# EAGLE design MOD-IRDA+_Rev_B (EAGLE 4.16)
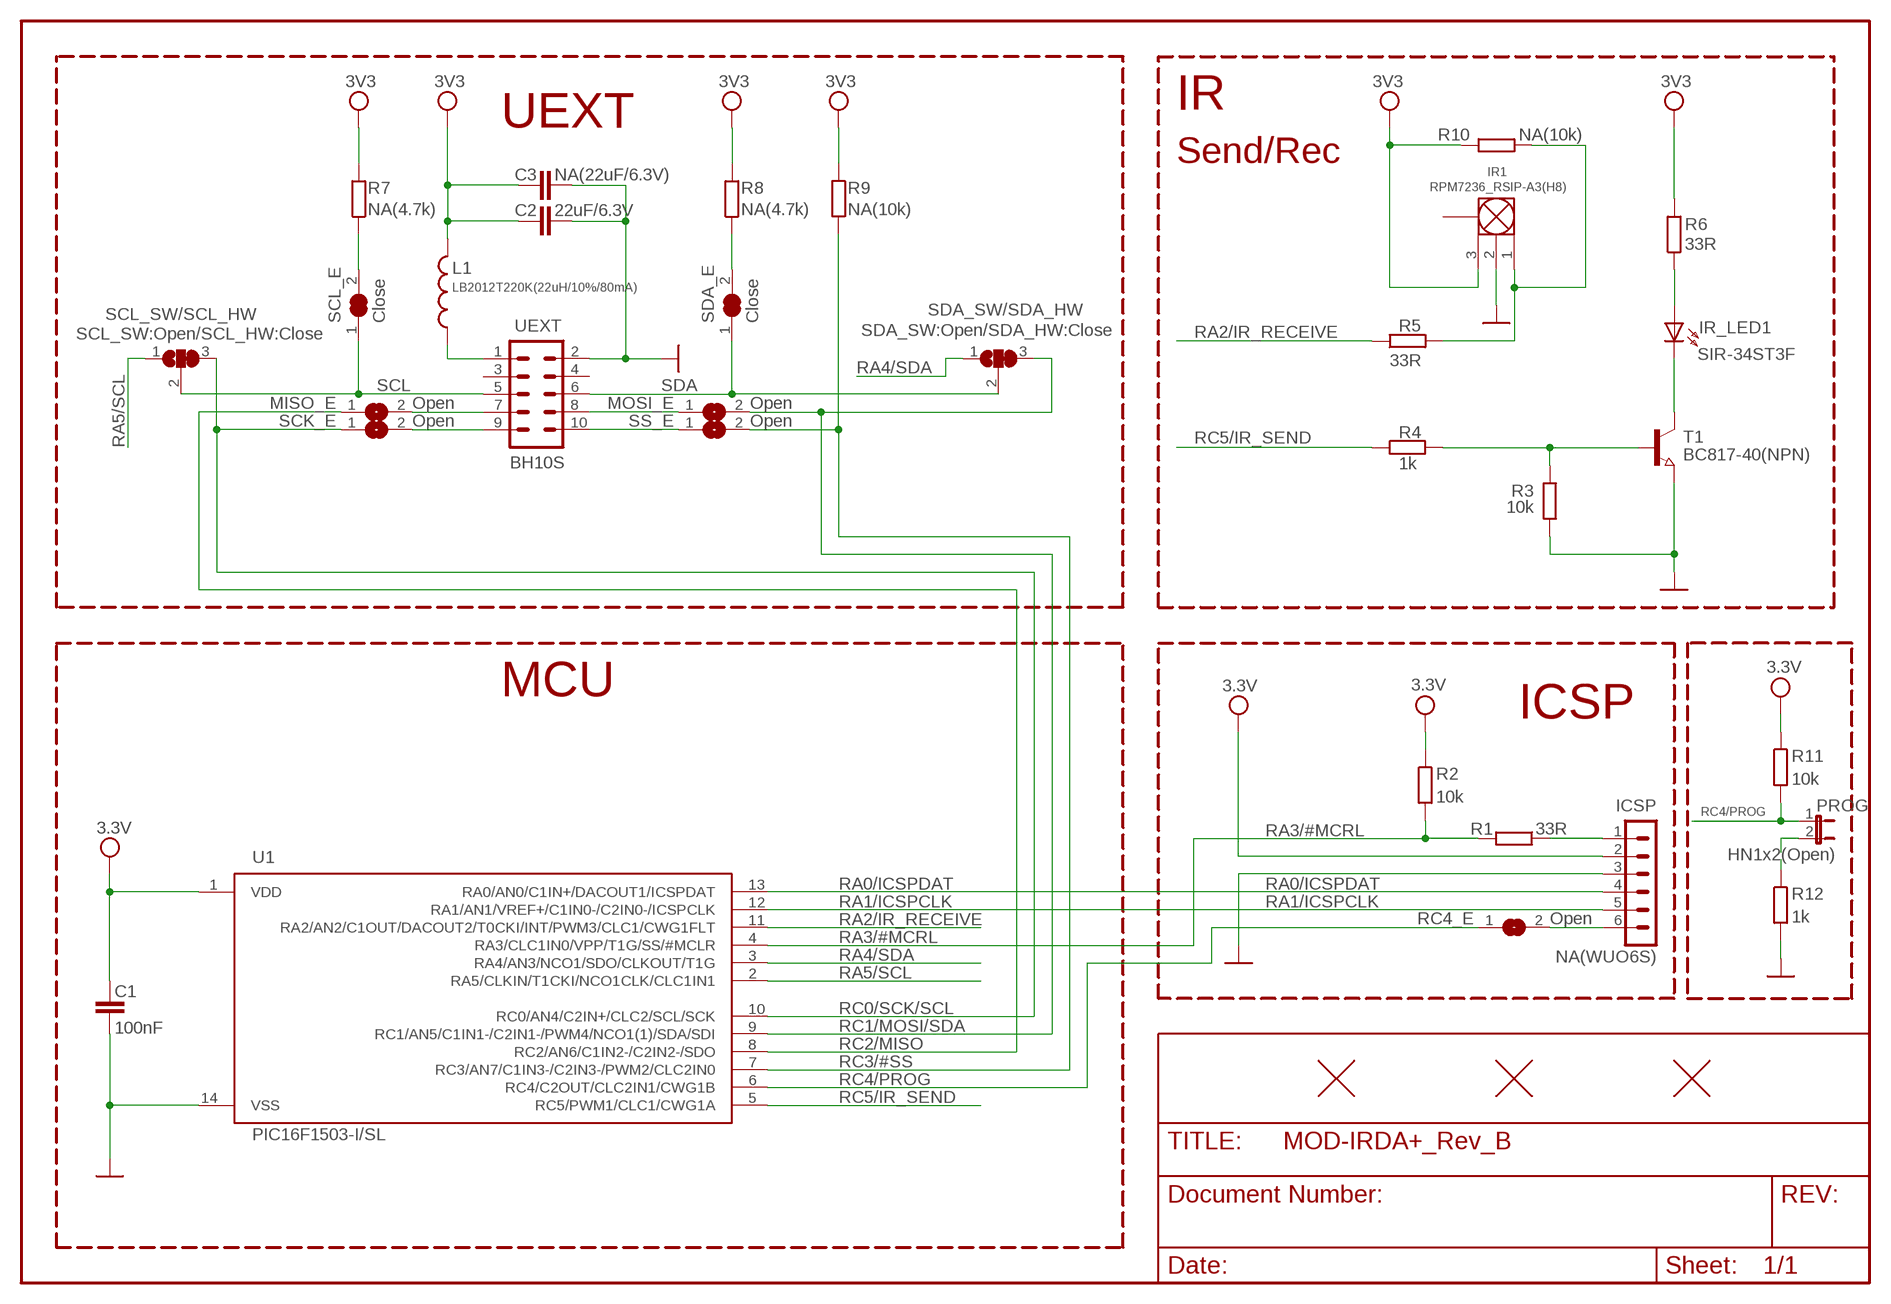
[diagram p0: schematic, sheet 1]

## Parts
C1  100nF  C-EUC0603_DWS  [C0603_DWS]
C2  22uF/6.3V  C-EUC0603_DWS  [C0603_DWS]
C3  NA(22uF/6.3V)  C-EUC0603_DWS  [C0603_DWS]
FID1  FIDUCIAL1X2  [FIDUCIAL-1X2]
FID2  FIDUCIAL1X2  [FIDUCIAL-1X2]
FID3  FIDUCIAL1X2  [FIDUCIAL-1X2]
ICSP  NA(WUO6S)  CON6WUO6S  [WU06S]
IR1  RPM7236_RSIP-A3(H8)  RPM7236  [RPM7236]
IR_LED1  SIR-34ST3F  LED3.0MM  [LED-3.0MM]
L1  LB2012T220K(22uH/10%/80mA)  L-USL0805_5MIL_DWS  [L0805_5MIL_DWS]
MISO_E  Open  SJSJ_SMALLER  [SJ_1_SMALLER]
MOSI_E  Open  SJSJ_SMALLER  [SJ_1_SMALLER]
PROG  HN1x2(Open)  JP1E  [JP1]
R1  33R  R-EU_R0603_5MIL_DWS  [R0603_5MIL_DWS]
R2  10k  R-EU_R0603_5MIL_DWS  [R0603_5MIL_DWS]
R3  10k  R-EU_R0603_5MIL_DWS  [R0603_5MIL_DWS]
R4  1k  R-EU_R0603_5MIL_DWS  [R0603_5MIL_DWS]
R5  33R  R-EU_R0603_5MIL_DWS  [R0603_5MIL_DWS]
R6  33R  R-EU_R0805_5MIL_DWS  [R0805_5MIL_DWS]
R7  NA(4.7k)  R-EU_R0603_5MIL_DWS  [R0603_5MIL_DWS]
R8  NA(4.7k)  R-EU_R0603_5MIL_DWS  [R0603_5MIL_DWS]
R9  NA(10k)  R-EU_R0603_5MIL_DWS  [R0603_5MIL_DWS]
R10  NA(10k)  R-EU_R0603_5MIL_DWS  [R0603_5MIL_DWS]
R11  10k  R-EU_R0603_5MIL_DWS  [R0603_5MIL_DWS]
R12  1k  R-EU_R0603_5MIL_DWS  [R0603_5MIL_DWS]
RC4_E  Open  SJSJ_SMALLER  [SJ_1_SMALLER]
SCK_E  Open  SJSJ_SMALLER  [SJ_1_SMALLER]
SCL_E  Close  SJSJ_1_SMALLER_CLOSE  [SJ_1_SMALLER_CLOSE]
SCL_SW/SCL_HW  SCL_SW:Open/SCL_HW:Close  SJ2W5  [SJ_2_SMALL_23_TIED]
SDA_E  Close  SJSJ_1_SMALLER_CLOSE  [SJ_1_SMALLER_CLOSE]
SDA_SW/SDA_HW  SDA_SW:Open/SDA_HW:Close  SJ2W5  [SJ_2_SMALL_23_TIED]
SS_E  Open  SJSJ_SMALLER  [SJ_1_SMALLER]
T1  BC817-40(NPN)  NPN-TRANSISTOR_SOT23  [SOT23]
U1  PIC16F1503-I/SL  PIC16F1503  [SOIC14]
UEXT  BH10S  ML10SMD  [ML10_PADS]

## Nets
GND: C1.2 C2.2 C3.2 ICSP.3 IR1.2(GND) R3.2 R12.2 T1.2(E) U1.14(VSS) UEXT.2
N$1: IR_LED1.K(C) T1.3(C)
N$2: IR1.1(VOUT) R5.2 R10.2
N$3: IR_LED1.A R6.1
N$4: R3.1 R4.2 T1.1(B)
N$5: MISO_E.2 UEXT.7
N$6: R7.1 SCL_E.2
N$7: R8.1 SDA_E.2
N$8: SCK_E.2 UEXT.9
N$9: ICSP.6 RC4_E.2
N$10: SS_E.1 UEXT.10
N$11: MOSI_E.1 UEXT.8
N$12: L1.1 UEXT.1
N$13: ICSP.1 R1.1
N$15: PROG.2 R12.1
RA0/ICSPDAT: ICSP.4 U1.13(RA0/AN0/C1IN+/DACOUT1/ICSPDAT)
RA1/ICSPCLK: ICSP.5 U1.12(RA1/AN1/VREF+/C1IN0-/C2IN0-/ICSPCLK)
RA2/IR_RECEIVE: R5.1 U1.11(RA2/AN2/C1OUT/DACOUT2/T0CKI/INT/PWM3/CLC1/CWG1FLT)
RA3/#MCRL: R1.2 R2.2 U1.4(RA3/CLC1IN0/VPP/T1G/SS/#MCLR)
RA4/SDA: SDA_SW/SDA_HW.1 U1.3(RA4/AN3/NCO1/SDO/CLKOUT/T1G)
RA5/SCL: SCL_SW/SCL_HW.1 U1.2(RA5/CLKIN/T1CKI/NCO1CLK/CLC1IN1)
RC0/SCK/SCL: SCK_E.1 SCL_SW/SCL_HW.3 U1.10(RC0/AN4/C2IN+/CLC2/SCL/SCK)
RC1/MOSI/SDA: MOSI_E.2 SDA_SW/SDA_HW.3 U1.9(RC1/AN5/C1IN1-/C2IN1-/PWM4/NCO1(1)/SDA/SDI)
RC2/MISO: MISO_E.1 U1.8(RC2/AN6/C1IN2-/C2IN2-/SDO)
RC3/#SS: R9.2 SS_E.2 U1.7(RC3/AN7/C1IN3-/C2IN3-/PWM2/CLC2IN0)
RC4/PROG: PROG.1 R11.2 RC4_E.1 U1.6(RC4/C2OUT/CLC2IN1/CWG1B)
RC5/IR_SEND: R4.1 U1.5(RC5/PWM1/CLC1/CWG1A)
SCL: SCL_E.1 SCL_SW/SCL_HW.2 UEXT.5
SDA: SDA_E.1 SDA_SW/SDA_HW.2 UEXT.6
VCC: C1.1 C2.1 C3.1 ICSP.2 IR1.3(VCC) L1.2 R2.1 R6.2 R7.2 R8.2 R9.1 R10.1 R11.1 U1.1(VDD) ; supply symbol labelled 3V3, 3.3V
Unconnected: IR1.P$4 IR1.P$5 UEXT.3 UEXT.4

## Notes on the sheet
- IR
- UEXT
- Send/Rec
- MCU
- ICSP

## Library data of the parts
C1-C3 = rcl:C-EU: CAPACITOR, European symbol
FID1-FID3 = SparkFunEagle-6-6-07:FIDUCIAL: Fiducial Alignment Points
ICSP = Penko:CON6: CONNECTORS - 6 PINS
IR1 = OLIMEX_DISCRET:RPM7236
IR_LED1 = DOUBLE-SIDE:LED
L1 = rcl:L-US: INDUCTOR, American symbol
MISO_E MOSI_E RC4_E SCK_E SCL_E SDA_E SS_E = jumper:SJ: SMD solder JUMPER
PROG = jumper:JP1E: JUMPER
R1-R12 = rcl:R-EU_: RESISTOR, European symbol
SCL_SW/SCL_HW SDA_SW/SDA_HW = jumper:SJ2W: SMD solder JUMPER
T1 = semicon-smd-ipc:NPN-TRANSISTOR_: NPN TRANSISTOR
U1 = OLIMEX_IC:PIC16F1503
UEXT = con-harting-ml:ML10: HARTING

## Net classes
1 PWR: width 0.203 mm, drill 0.076 mm, clearance 0.4 mm

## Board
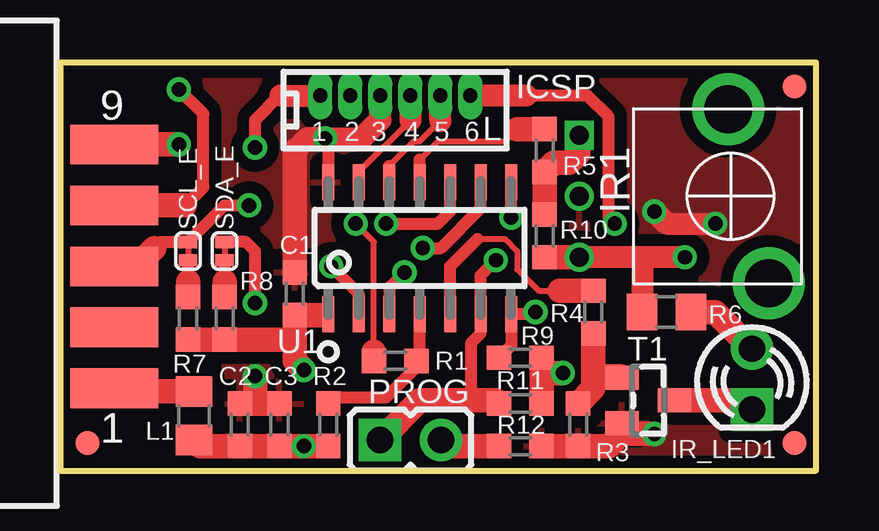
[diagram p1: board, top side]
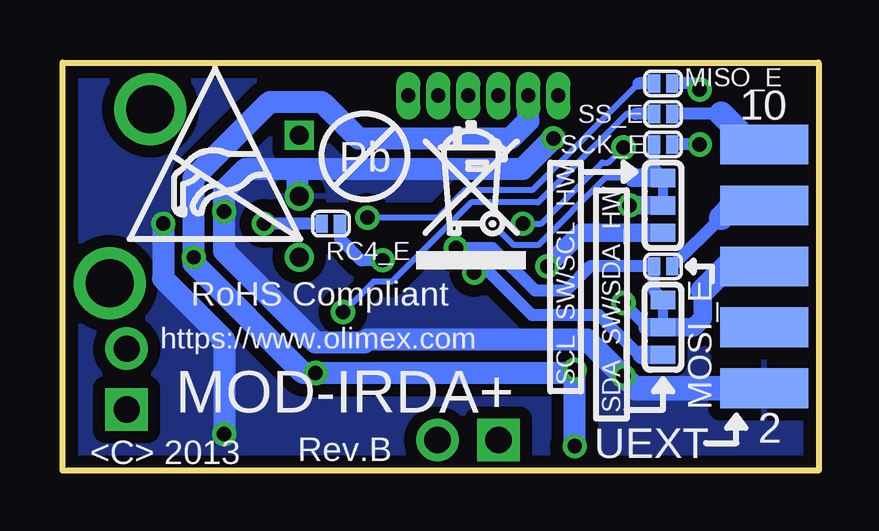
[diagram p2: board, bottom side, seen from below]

Size 31.5 x 17 mm. Coordinates in mm from the lower left corner, seen from the top.
Outline: 0,0 31.5,0 31.5,17 0,17 0,0
Copper layers (1+16): Top 0.035mm / dielectric 1.5mm / Bottom 0.035mm
Design rules "default": minimum track width 10mil, minimum drill 23mil, track to track 10mil, track to pad 10mil, pad to pad 10mil, via to via 10mil, smd to smd 1mil, copper to edge 10mil, drill to drill 8mil, minimum pad ring 7mil, minimum via ring 8mil, stop-mask expansion 4mil, vias tented up to drill 30mil, thermal gap 20mil

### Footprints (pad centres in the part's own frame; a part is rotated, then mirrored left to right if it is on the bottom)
C0603_DWS = smd 1.016 x 1.016: 1 -0.889,0; 2 0.889,0
FIDUCIAL-1X2 = smd 1 x 1: 1 0,0
WU06S = drill 0.6 pad 0.991 long: 1 -3.125,0; 2 -1.875,0; 3 -0.625,0; 4 0.625,0; 5 1.875,0; 6 3.125,0
RPM7236 = drill 0.8 square: 1 -2.54,-6.3 | drill 0.8 round: 2 0,-6.3; 3 2.54,-6.3 | drill 2 round: P$4 -3.63,-0.1; P$5 3.63,1.6
LED-3.0MM = drill 1.092 pad 1.778 round: A -1.27,0 | drill 1.092 pad 1.778 square: K 1.27,0
L0805_5MIL_DWS = smd 1.27 x 1.524: 1 -1.016,0; 2 1.016,0
SJ_1_SMALLER = smd 0.508 x 0.762: 1 -0.381,0; 2 0.381,0
JP1 = drill 1.1 pad 1.778 square: 1 0,-1.27 | drill 1.1 pad 1.778 round: 2 0,1.27
R0603_5MIL_DWS = smd 1.016 x 1.016: 1 -0.889,0; 2 0.889,0
R0805_5MIL_DWS = smd 1.27 x 1.524: 1 -1.016,0; 2 1.016,0
SJ_1_SMALLER_CLOSE = smd 0.508 x 0.762: 1 -0.381,0; 2 0.381,0
SJ_2_SMALL_23_TIED = smd 0.762 x 1.016: 1 -1.143,0; 2 0,0; 3 1.143,0
SOT23 = smd 1 x 1.4: 1 -0.95,-1.1; 2 0.95,-1.1; 3 0,1.1
SOIC14 = smd 0.5 x 1.5: 1 -3.81,-2.75; 2 -2.54,-2.75; 3 -1.27,-2.75; 4 0,-2.75; 5 1.27,-2.75; 6 2.54,-2.75; 7 3.81,-2.75; 8 3.81,2.75; 9 2.54,2.75; 10 1.27,2.75; 11 0,2.75; 12 -1.27,2.75; 13 -2.54,2.75; 14 -3.81,2.75
ML10_PADS = smd 1.651 x 3.683: 1 -5.08,-0.229; 3 -2.54,-0.229; 5 0,-0.229; 7 2.54,-0.229; 9 5.08,-0.229 | smd 1.651 x 3.683 bottom: 2 -5.08,-0.229; 4 -2.54,-0.229; 6 0,-0.229; 8 2.54,-0.229; 10 5.08,-0.229

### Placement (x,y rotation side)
C1  9.78,7.37 90 top
C2  7.49,1.91 90 top
C3  9.14,1.91 90 top
FID1  1.14,1.14 0 top
FID2  30.61,1.14 0 top
FID3  30.61,16 0 top
ICSP  13.97,15.62 0 top
IR1  27.94,11.43 270 top
IR_LED1  28.83,3.81 270 top
L1  5.59,2.29 270 top
MISO_E  6.48,16.13 0 bottom
MOSI_E  6.48,8.51 180 bottom
PROG  14.61,1.27 270 top
R1  13.97,4.57 0 top
R2  11.18,1.91 90 top
R3  21.59,1.91 270 top
R4  22.23,6.6 270 top
R5  20.19,13.34 270 top
R6  25.27,6.6 180 top
R7  5.33,6.35 270 top
R8  6.86,6.35 270 top
R9  19.18,4.7 180 top
R10  20.19,9.78 90 top
R11  19.18,2.79 180 top
R12  19.18,1.02 0 top
RC4_E  20.32,10.29 180 bottom
SCK_E  6.48,13.59 0 bottom
SCL_E  5.33,9.14 270 top
SCL_SW/SCL_HW  6.48,11.05 90 bottom
SDA_E  6.86,9.14 270 top
SDA_SW/SDA_HW  6.48,5.97 90 bottom
SS_E  6.48,14.86 180 bottom
T1  24.51,2.92 270 top
U1  14.99,9.27 0 top
U$1  [ESD_SYMBOL]  28.7,9.65 0 bottom
U$2  [RECYCLE_BIN1/8]  16.76,8.38 0 bottom
U$3  [PB_SMALL]  18.92,13.08 0 bottom
UEXT  2.03,8.51 90 top

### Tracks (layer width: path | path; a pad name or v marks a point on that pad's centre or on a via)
GND  (via drill 0.6)
  Top 0.508: U1.14 11.18,13.72 v11.05,13.84
  Top 0.914: ICSP.3 13.35,14.62 12.57,13.84 v11.05,13.84 10.29,13.84 9.78,13.34 | v24.77,10.79 25.27,10.29 v27.3,10.29
  Top 1.016: 8.13,2.79 C3.2 | 9.78,13.34 C1.2 | v8.13,3.94 8.13,2.79 | 8.13,2.79 C2.2 | R12.2 R3.2 22.86,1.02 23.37,1.52 | v24.77,1.52 23.37,1.52 | T1.2 23.37,1.93 23.37,1.52
  Bottom 0.914: v11.05,13.84 12.32,12.57 21.72,12.57 | 7.62,3.43 v8.13,3.94 9.65,5.46 18.8,5.46 18.92,5.33 20.95,5.33 24.77,9.14 v24.77,10.79 24.77,11.68 23.88,12.57 21.72,12.57 | v24.77,1.52 24.77,5.46 27.3,8 v27.3,10.29 | IR1.2 21.72,11.51 21.72,12.57
  Bottom 1.016: UEXT.2 7.62,3.43
  pour Bottom (isolate 0.508): -10.54,19.3 38.1,19.3 38.1,-2.54 -10.54,-2.54
  pour Top (isolate 0.508): -9.53,18.03 33.02,18.03 33.02,-1.27 -9.53,-1.27
N$1
  Top 1.016: T1.3 28.45,2.92 IR_LED1.K
N$2
  Top 1.016: IR1.1 21.59,13.92 21.59,13.21 21.21,12.83 20.57,12.83 R5.2 R10.2
N$3
  Top 1.016: R6.1 27.3,6.6 IR_LED1.A
N$4
  Top 1.016: R3.1 22.23,3.43 22.23,3.94 | 22.23,3.94 R4.2 | T1.1 23.34,3.94 22.23,3.94
N$5  (via drill 0.6)
  Top 0.508: 5.21,11.05 5.97,11.81 5.97,14.86 v4.95,15.88
  Top 1.016: UEXT.7 5.21,11.05
  Bottom 0.508: v4.95,15.88 5.21,16.13 MISO_E.2
N$6
  Top 0.508: 5.33,7.87 SCL_E.2
  Top 1.016: R7.1 5.33,7.87
N$7
  Top 0.508: 6.86,7.87 SDA_E.2
  Top 1.016: R8.1 6.86,7.87
N$8  (via drill 0.6)
  Top 1.016: UEXT.9 v4.95,13.59
  Bottom 0.508: v4.95,13.59 SCK_E.2
N$9  (via drill 0.6)
  Top 0.508: v23.11,10.29 22.86,10.54 22.86,14.73 21.97,15.62 19.43,15.62
  Top 0.914: 19.43,15.62 ICSP.6
  Bottom 0.508: RC4_E.2 v23.11,10.29
N$10
  Bottom 0.508: UEXT.10 2.52,13.34 | 4.06,14.86 SS_E.1
  Bottom 0.762: 2.52,13.34 2.54,13.34
  Bottom 1.016: 2.54,13.34 4.06,14.86
N$11
  Bottom 0.508: 4.06,10.54 MOSI_E.1
  Bottom 1.016: UEXT.8 3.56,11.05 4.06,10.54
N$12
  Top 1.016: UEXT.1 2.39,3.3 L1.1
N$13  (via drill 0.6)
  Top 0.254: 13.08,4.95 13.08,9.53 v12.32,10.29
  Top 0.508: 9.19,15.62 9.14,15.62 8.13,14.61 v8.13,13.46
  Top 0.914: 9.19,15.62 ICSP.1
  Top 1.016: R1.1 13.08,4.95
  Bottom 0.254: v12.32,10.29 11.56,10.29 9.02,12.83 8.76,12.83 v8.13,13.46
N$15
  Top 1.016: R12.1 16.13,1.02 PROG.2
RA0/ICSPDAT
  Top 0.254: U1.13 12.45,12.45 14.61,14.61
  Top 0.508: ICSP.4
  Top 0.914: 14.61,14.61 ICSP.4
RA1/ICSPCLK
  Top 0.254: 13.72,12.7 14.73,13.72 14.99,13.72 15.85,14.57
  Top 0.508: U1.12 13.72,12.7
  Top 0.914: 15.85,14.57 ICSP.5
RA2/IR_RECEIVE
  Top 0.254: 14.99,12.95 15.75,13.72 18.54,13.72 19.05,14.22
  Top 0.508: U1.11 14.99,12.95
  Top 1.016: 19.05,14.22 R5.1
RA3/#MCRL
  Top 0.508: R2.2 11.43,3.05 13.59,3.05 14.86,4.32 R1.2 14.99,4.57 U1.4
RA4/SDA  (via drill 0.6)
  Top 0.508: v14.35,8.26 13.72,7.62 U1.3
  Bottom 0.508: v14.35,8.26 13.72,8.26 11.94,6.48 9.14,6.48 7.49,4.83 7.37,4.83
  Bottom 0.762: SDA_SW/SDA_HW.1 7.37,4.83
RA5/SCL  (via drill 0.6)
  Top 0.508: v11.3,8.51 12.45,7.37 U1.2
  Bottom 0.762: v11.3,8.51 9.91,9.91 SCL_SW/SCL_HW.1
RC0/SCK/SCL  (via drill 0.6)
  Top 0.508: v13.59,10.29 15.75,10.29 16.26,10.79 U1.10
  Bottom 0.254: v13.59,10.29 12.7,9.4 11.68,9.4 8.89,12.19 7.75,12.19
  Bottom 0.508: SCL_SW/SCL_HW.3 6.86,12.57 SCK_E.1
  Bottom 0.762: SCL_SW/SCL_HW.3 7.75,12.19
RC1/MOSI/SDA  (via drill 0.6)
  Top 0.508: U1.9 17.53,10.92 15.88,9.27 v15.11,9.27
  Bottom 0.508: v15.11,9.27 13.59,9.27 11.81,7.49 10.54,7.49 9.53,8.51 MOSI_E.2 6.86,7.49 SDA_SW/SDA_HW.3
RC2/MISO  (via drill 0.6)
  Top 0.508: v18.8,10.54 U1.8
  Bottom 0.254: 7.49,16.13 11.94,11.68 14.73,11.68 15.88,10.54 v18.8,10.54
  Bottom 0.508: MISO_E.1 7.49,16.13
RC3/#SS  (via drill 0.6)
  Top 0.508: R9.2 18.8,5.21 U1.7 19.73,6.52 v19.81,6.6
  Bottom 0.254: 7.62,14.86 8,14.86 11.68,11.18 14.48,11.18 17.78,7.87 18.54,7.87 v19.81,6.6
  Bottom 0.508: SS_E.2 7.62,14.86
RC4/PROG  (via drill 0.6)
  Top 0.508: v18.16,8.76 17.53,8.13 U1.6 17.53,5.71 17.14,5.33 17.14,2.92
  Top 1.016: R11.2 18.16,2.92 17.14,2.92 14.99,2.92 PROG.1
  Bottom 0.508: v18.16,8.76 19.05,8.76 19.94,9.65 RC4_E.1
RC5/IR_SEND
  Top 0.254: 17.4,9.65 18.54,9.65 19.05,9.14 19.05,8.38 19.94,7.49 20.83,7.49
  Top 0.508: 17.4,9.65 16.26,8.51 U1.5
  Top 1.016: 20.83,7.49 R4.1
SCL  (via drill 0.6)
  Top 0.508: v7.87,11.05 6.86,11.05 SCL_E.1 4.19,9.53 3.94,9.27
  Top 1.016: UEXT.5 3.17,8.51 3.94,9.27
  Bottom 0.762: v7.87,11.05 SCL_SW/SCL_HW.2
SDA  (via drill 0.6)
  Top 0.508: SDA_E.1 7.75,9.53 8.13,9.14 v8.13,6.99
  Bottom 0.508: 7.11,5.97 v8.13,6.99
  Bottom 0.762: 4.83,7.49 4.83,6.35 5.21,5.97 SDA_SW/SDA_HW.2 7.11,5.97
  Bottom 1.016: UEXT.6 3.81,8.51 4.83,7.49
VCC  (via drill 0.6)
  Top 0.508: 10.88,6.48 11.18,6.48 U1.1
  Top 0.914: 24.26,8.89 IR1.3 | v26.04,8.89 24.26,8.89 | 24.26,8.89 R6.2
  Top 1.016: v10.16,1.02 R2.1 C3.1 C2.1 5.84,1.02 L1.2 | R7.2 R8.2 9.78,5.46 | 20.07,4.06 R11.1 | v20.95,4.06 20.07,4.06 | 20.07,4.06 R9.1 | IR1.3 R10.1 | v10.16,4.19 9.78,4.57 9.78,5.46 | 9.78,5.46 C1.1 10.88,6.48
  Bottom 0.914: ICSP.2 12.1,14.57 12.83,13.84 19.18,13.84 20.7,15.37 22.86,15.37 26.04,12.19 v26.04,8.89 26.04,8.64 21.46,4.06 v20.95,4.06 10.16,4.06 | v10.16,1.02 10.16,4.06 | 10.16,4.06 v10.16,4.19

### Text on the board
bNames: RoHS Compliant | https://www.olimex.com | MOD-IRDA+ | Rev.B | <C> 2013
